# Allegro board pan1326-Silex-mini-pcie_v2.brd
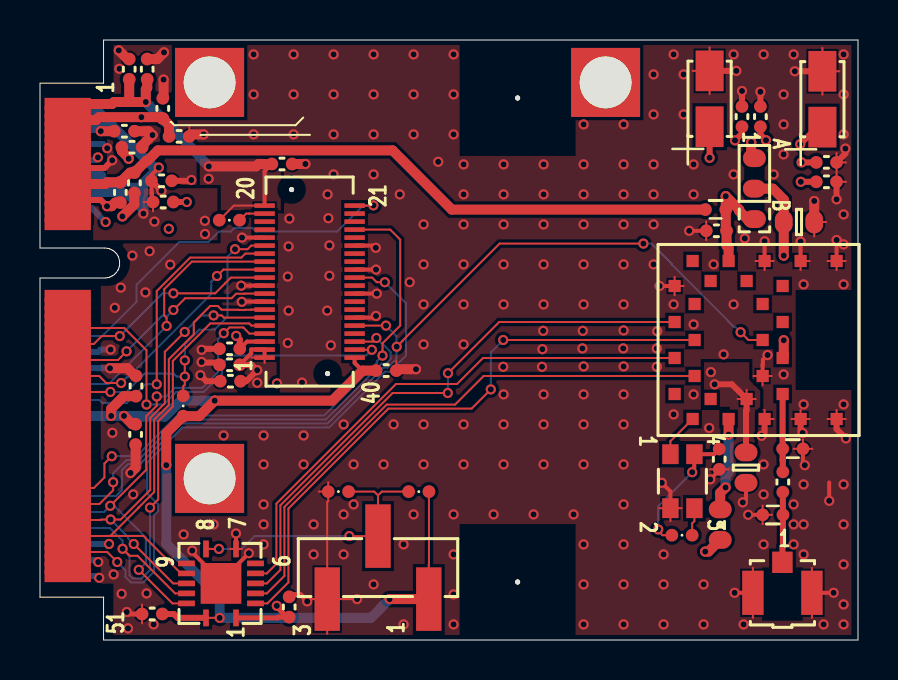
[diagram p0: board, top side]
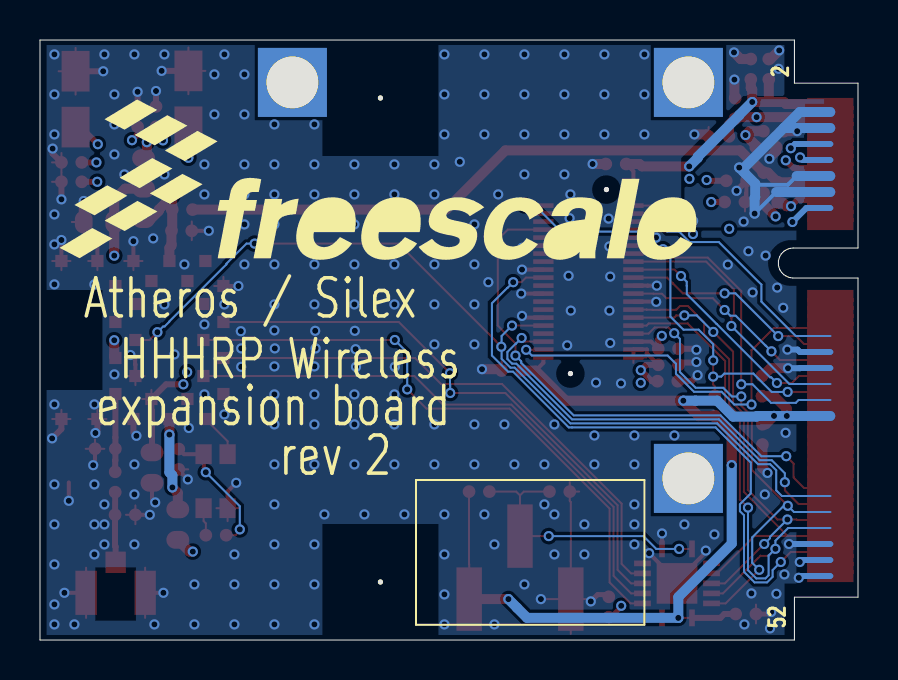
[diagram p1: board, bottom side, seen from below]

Outline 40.9 x 30 mm; copper layers: TOP, GND, PWR, BOTTOM. Coordinates in mm from the lower left corner of the outline.
Outline path: 0,27.84 0,19.6 3.24,19.6 3.4,19.58 3.48,19.56 3.64,19.48 3.7,19.44 3.84,19.3 3.92,19.16 3.98,18.96 3.98,18.74 3.96,18.66 3.92,18.54 3.9,18.5 3.82,18.38 3.7,18.26 3.6,18.2 3.48,18.14 3.4,18.12 3.26,18.1 0,18.1 0,2.14 3.18,2.14 3.18,0 40.9,0 40.9,30 3.18,30 3.18,27.84 0,27.84

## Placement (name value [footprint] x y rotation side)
C2  ASSEMBLE 0R  [CC0402_25]  37.14 7.9 270 top
C7  0.1uF  [CC0402_25]  5.61 1.3 180 top
C12  2.2UF  [CC0603_OV]  35.3 8.62 270 top
C15  1.0UF  [CC0402_25]  33.82 20.46 180 top
C16  2.2UF  [CC0603_OV]  37.95 20.9 0 top
C17  0.1uF  [CC0402_25]  12.46 1.65 90 top
C18  0.1uF  [CC0402_25]  33.96 9.04 270 top
C19  0.1uF  [CC0402_25]  9.48 13.76 180 top
C20  0.1uF  [CC0402_25]  9.48 14.56 180 top
C21  0.1uF  [CC0402_25]  9.52 12.94 180 top
C22  0.1uF  [CC0402_25]  17.31 13.47 0 top
C23  0.1uF  [CC0402_25]  12.1 23.8 0 top
C24  47uF  [CC3216]  39.12 27.04 90 top
C25  47uF  [CC3216]  33.48 27.06 90 top
C26  0.1uF  [CC0402_25]  35.1 26.17 90 top
C27  0.1uF  [CC0402_25]  39.32 23.88 0 top
C28  0.01UF  [CC0402_25]  36.02 26.17 90 top
C29  0.01UF  [CC0402_25]  39.32 22.91 0 top
C46  100PF  [CC0402_25]  4.22 25.44 0 top
C47  0.01UF  [CC0402_25]  4.6 24.64 0 top
C48  0.01UF  [CC0402_25]  6.08 22.96 0 top
C49  100PF  [CC0402_25]  6.16 21.9 0 top
C54  0.01UF  [CC0402_25]  4.02 22.38 270 top
C55  100PF  [CC0402_25]  4.72 22.86 270 top
C56  0.01UF  [CC0402_25]  6.96 25.18 0 top
C57  100PF  [CC0402_25]  6.14 26.58 90 top
C58  0.01UF  [CC0402_25]  4.46 28.54 90 top
C59  100PF  [CC0402_25]  5.36 28.54 90 top
C60  0.01UF  [CC0402_25]  4.78 10.28 270 top
C61  100PF  [CC0402_25]  4.8 12.7 90 top
J1  MINIPCI EDGE CONNECTOR  [CON2X26_MINI_PCIE_HALFSIZE]  13.38 15 270 top
J2  HDR 2X20  [HDR_2X20_0P4_SM]  13.48 17.92 90 top
J3  HDR 1X3  [HDR103_STAG_SM]  16.9 3.62 90 top
J4  U.FL  [CON_3_UFL_R_SMT]  37.12 2.36 0 top
L2  TBD  [IND_0402]  37.64 9.56 0 top
L3  TBD  [IND_0402]  36.64 6.26 180 top
L5  120 Ohm  [IND_0402]  33.78 21.52 0 top
NOREF  -  []  -0.02 17.56 0 top
NOREF#2  -  []  3.18 0 90 top
NOREF#3  -  []  65.58 169.66 90 top
NOREF#4  -  [unnamed#2]  8.48 27.88 0 top
NOREF#5  -  []  63.32 189.4 90 top
NOREF#6  -  [unnamed#2]  28.28 27.88 0 top
NOREF#7  -  []  3.18 30 0 top
NOREF#8  -  []  40.9 0 90 top
NOREF#9  -  []  -179.5 -280.6 0 top
NOREF#10  -  []  3.18 27.84 90 top
NOREF#11  -  []  0 19.6 90 top
NOREF#12  -  []  69.78 196.44 0 top
NOREF#13  -  [unnamed#2]  8.48 8.08 0 top
NOREF#14  -  []  399.68 196.44 0 top
NOREF#15  -  []  0 2.14 90 top
NOREF#16  -  []  63.4 174.28 90 top
NOREF#17  -  []  0 27.84 0 top
NOREF#18  -  []  39.92 19.5 180 bottom
R5  10.0K  [RC0402_25]  32.1 5.24 180 top
R6  10.0K  [RC0402_25]  18.94 7.42 180 top
R7  10.0K  [RC0402_25]  14.92 7.42 0 top
R8  22K  [RC0402_25]  7.16 11.7 90 top
R9  10.0K  [RC0402_25]  9.47 20.99 0 top
R13  0  [R603-X2]  35.72 23.33 270 top
R14  0  [RC0603_OV]  34.01 5.77 90 top
U1  PAN1326  [LGA24_0P9_9P2X9P7]  34.43 15 270 top
U4  TXB0104  [QFN14_RGY]  9.05 2.83 90 top
Y1  32.7680KHZ  [XTLOSC4_3P3X1P6_SM]  32.12 7.94 270 top

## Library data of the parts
C2 C7 C12 C15-C29 C46-C49 C54-C61 = CAP_NP
J1 = MINI_PCI_LATCH_52P
J2 = CONN_HDR_20X2
J3 = CONN_HDR_3X1
J4 = UFL
L2 L3 = BEAD
L5 = INDUCTOR_FERRITE
R5-R9 R14 = RES
R13 = RES_0603_X2: Tolerance: X; User Part Number: 470-80217
U1 = ENW898_24P
U4 = TXB0104
Y1 = OSC_4P

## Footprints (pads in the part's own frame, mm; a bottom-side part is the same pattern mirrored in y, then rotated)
CC0402_25
  round 0.635 smd: 1(-0.508,0) 2(0.508,0)
CC0603_OV
  oval 0.889x1.143 smd: 1(-0.762,0) 2(0.762,0)
CC3216
  rect 2.032x1.397 smd: 1(-1.397,0) 2(1.397,0)
CON2X26_MINI_PCIE_HALFSIZE
  round 0.254 hole 2.591 unplated: (-12.1,10.5) (12.1,10.5)
  rect 0.61x2.311 smd: 1(-11.8,-11.994) 2(-11.4,-11.994) 3(-11,-11.994) 4(-10.6,-11.994) 5(-10.2,-11.994) 6(-9.8,-11.994) 7(-9.4,-11.994) 8(-9,-11.994) 9(-8.6,-11.994) 10(-8.2,-11.994) 11(-7.8,-11.994) 12(-7.4,-11.994) 13(-7,-11.994) 14(-6.6,-11.994) 15(-6.2,-11.994) 16(-5.8,-11.994) 17(-2.2,-11.994) 18(-1.8,-11.994) 19(-1.4,-11.994) 20(-1,-11.994) 21(-0.6,-11.994) 22(-0.2,-11.994) 23(0.2,-11.994) 24(0.6,-11.994) 25(1,-11.994) 26(1.4,-11.994) 27(1.8,-11.994) 28(2.2,-11.994) 29(2.6,-11.994) 30(3,-11.994) 31(3.4,-11.994) 32(3.8,-11.994) 33(4.2,-11.994) 34(4.6,-11.994) 35(5,-11.994) 36(5.4,-11.994) 37(5.8,-11.994) 38(6.2,-11.994) 39(6.6,-11.994) 40(7,-11.994) 41(7.4,-11.994) 42(7.8,-11.994) 43(8.2,-11.994) 44(8.6,-11.994) 45(9,-11.994) 46(9.4,-11.994) 47(9.8,-11.994) 48(10.2,-11.994) 49(10.6,-11.994) 50(11,-11.994) 51(11.4,-11.994) 52(11.8,-11.994)
CON_3_UFL_R_SMT
  rect 1.016x1.067 smd: 1(0,1.524)
  rect 1.067x2.21 smd: 2(-1.476,0) 3(1.476,0)
HDR103_STAG_SM
  rect 3.175x1.27 smd: 1(-1.575,-2.54) 2(1.575,0) 3(-1.575,2.54)
HDR_2X20_0P4_SM
  round 0.254 hole 0.66 unplated: (-4.6,-0.9) (4.6,0.9)
  rect 0.229x1.016 smd: 1(-3.8,2.25) 2(-3.4,2.25) 3(-3,2.25) 4(-2.6,2.25) 5(-2.2,2.25) 6(-1.8,2.25) 7(-1.4,2.25) 8(-1,2.25) 9(-0.6,2.25) 10(-0.2,2.25) 11(0.2,2.25) 12(0.6,2.25) 13(1,2.25) 14(1.4,2.25) 15(1.8,2.25) 16(2.2,2.25) 17(2.6,2.25) 18(3,2.25) 19(3.4,2.25) 20(3.8,2.25) 21(3.8,-2.25) 22(3.4,-2.25) 23(3,-2.25) 24(2.6,-2.25) 25(2.2,-2.25) 26(1.8,-2.25) 27(1.4,-2.25) 28(1,-2.25) 29(0.6,-2.25) 30(0.2,-2.25) 31(-0.2,-2.25) 32(-0.6,-2.25) 33(-1,-2.25) 34(-1.4,-2.25) 35(-1.8,-2.25) 36(-2.2,-2.25) 37(-2.6,-2.25) 38(-3,-2.25) 39(-3.4,-2.25) 40(-3.8,-2.25)
IND_0402
  round 0.635 smd: 1(-0.508,0) 2(0.508,0)
LGA24_0P9_9P2X9P7
  rect 0.61x0.61 smd: 1(-2.7,-2.7) 2(-1.8,-1.7) 3(-0.9,-2.7) 4(0,-1.7) 5(0.9,-2.7) 6(1.8,-1.7) 7(2.7,-2.7) 8(3.95,-1.8) 9(2.95,-0.9) 10(3.95,0) 11(2.95,0.9) 12(3.95,1.8) 13(2.7,2.7) 14(1.8,1.7) 15(0.9,2.7) 16(0,1.7) 17(-0.9,2.7) 18(-1.8,1.7) 19(-2.7,2.7) 20(-3.95,1.8) 21(-2.95,0.9) 22(-3.95,0) 23(-2.95,-0.9) 24(-3.95,-1.8) A(-3.95,3.6) B(3.95,3.6) C(-3.95,5.4) D(3.95,5.4)
QFN14_RGY
  rect 0.838x0.279 smd: 1(-1.725,-0.75) 7(1.725,-0.75) 8(1.725,0.75) 14(-1.725,0.75)
  rect 0.279x0.838 smd: 2(-1,-1.725) 3(-0.5,-1.725) 4(0,-1.725) 5(0.5,-1.725) 6(1,-1.725) 9(1,1.725) 10(0.5,1.725) 11(0,1.725) 12(-0.5,1.725) 13(-1,1.725)
  rect 2.032x2.032 smd: 15(0,0)
R603-X2
  oval 0.889x1.143 smd: 1(-0.762,0) 2(0.762,0) 3(2.286,0)
RC0402_25
  round 0.635 smd: 1(-0.508,0) 2(0.508,0)
RC0603_OV
  oval 0.889x1.143 smd: 1(-0.762,0) 2(0.762,0)
unnamed#2
  rect 3.45x3.45 hole 2.591: (0,0)
XTLOSC4_3P3X1P6_SM
  rect 0.991x0.813 smd: 1(-1.35,-0.6) 2(1.35,-0.6) 3(1.35,0.6) 4(-1.35,0.6)

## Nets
GND: C7.2 C12.2 C15.2 C16.2 C17.2 C18.2 C19.2 C20.2 C21.2 C22.2 C23.2 C24.2 C25.2 C26.2 C27.2 C28.2 C29.2 C46.2 C47.2 C48.2 C49.2 C54.2 C55.2 C56.2 C57.2 C58.2 C59.2 C60.2 C61.2 J1.6(1.5V_1) J1.8(UIM_PWR) J1.9(GND1) J1.13(REFCLK+) J1.14(UIM_RESET) J1.24(+3.3VAUX) J1.26(GND9) J1.48(1.5V_3) J1.50(GND12) J1.52(3.3V_2) J2.8(B4) J2.10(B5) J2.16(B8) J2.26(B13) J2.29(A15) J2.32(B16) J2.35(A18) J3.3 J4.2(GND1) J4.3(GND2) L2.2 L3.2 R7.1 U1.1(GND1) U1.12(GND2) U1.14(GND3) U1.20(GND4#20) U1.A(GND4#A) U1.B(GND5) U1.C(GND6) U1.D(GND7) U4.7(GND) U4.15(EXP) Y1.2(GND)
BT_ACTIVE: J1.41(RESERVED5) J2.24(B12)
BT_CLK_REQ: J2.17(A9)
BT_CLKOUT: J2.22(B11)
BT_DISABLE: J2.23(A12)
BT_FREQUENCY: J2.37(A19)
BT_HOST_WAKE: J1.43(RESERVED6) J2.38(B19)
BT_PRIORITY: J2.25(A13)
BT_RESET_B: J1.42(LED_WWAN#) J2.36(B18) U1.16(S\H\U\T\D\)
BT_RF_3V3: C12.1 C20.1 C25.1 C26.1 C28.1 C56.1 C57.1 J1.3(RESERVED1) J2.3(A2) R13.1 U1.11(CL1.5_LDO_IN)
BT_UART_CTS: J1.45(RESERVED7) J2.6(B3) U4.11(B3)
BT_UART_CTS_1V8: U1.3(HCI_CTS) U4.4(A3)
BT_UART_RTS: J1.44(LED_WLAN#) J2.4(B2) U4.13(B1)
BT_UART_RTS_1V8: U1.4(HCI_RTS) U4.2(A1)
BT_UART_RX: J1.47(RESERVED8) J2.7(A4) U4.10(B4)
BT_UART_RX_1V8: U1.5(HCI_RX) U4.5(A4)
BT_UART_TX: J1.46(LED_WPAN#) J2.5(A3) U4.12(B2)
BT_UART_TX_1V8: U1.6(HCI_TX) U4.3(A2)
BT_VDDIO_1V8: C15.1 C17.1 C18.1 C24.1 C27.1 C29.1 L5.2 R5.2 R13.3 R14.1 U1.22(VDD_IO) U4.1(VCCA) Y1.4(VDD)
CLK32K: U1.8(SLOW_CLK_IN) Y1.1(CLKOUT)
DCDC_VDDIO_3V3: C7.1 C22.1 C23.1 C58.1 C59.1 C60.1 C61.1 J1.1(WAKE#) J1.32(SMB_DATA) J2.20(B10) J2.40(B20) J3.1 R6.1 R8.1 R9.1 U4.14(VCCB)
HMODE0: J2.19(A10) R9.2
WIFI_SDIO_CLK: J1.25(PERP0) J2.9(A5)
WIFI_SDIO_CMD: J1.29(GND5) J2.15(A8) R8.2
WIFI_SDIO_DAT0: J1.23(PERN0) J2.11(A6)
WIFI_SDIO_DAT1: J1.27(GND4) J2.12(B6)
WIFI_SDIO_DAT2: J1.28(1.5V_2) J2.13(A7)
WIFI_SDIO_DAT3: J1.30(SMB_CLK) J2.14(B7)
WL_RF_1V8: C54.1 C55.1 J1.11(REFCLK-) L5.1
WL_RF_3V3: C19.1 C21.1 C46.1 C47.1 C48.1 C49.1 J1.2(3.3V_1) J1.4(GND7) J1.10(UIM_DATA) J1.12(UIM_CLK) J2.1(A1) J2.2(B1)
WLAN_ACTIVE: J1.49(RESERVED9) J2.30(B15)
WLAN_RESET_B: J1.22(PERST#) J2.21(A11)
WLAN_WAKE: J1.21(GND3) J2.39(A20)
N16415: R5.1 Y1.3(CLKOE)
N18192: C2.2 J4.1(CTR) L3.1
N18200: C2.1 L2.1 U1.13(RF)
N28121: J3.2 R6.2 R7.2 U4.8(OE)
N39460: C16.1 R13.2 U1.15(MLDO_IN)
N39860: R14.2 U1.10(MLDO_OUT)

Pads without a net: J1 5 7 15 16 17 18 19 20 31 33 34 35 36 37 38 39 40 51; J2 18 27 28 31 33 34; U1 2 7 9 17 18 19 21 23 24; U4 6 9

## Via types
v1: diameter 0.508, hole 0.305, TOP to BOTTOM, 349 vias

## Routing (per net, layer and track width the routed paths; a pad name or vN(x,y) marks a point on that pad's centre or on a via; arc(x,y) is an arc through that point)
GND: length 120
  TOP w0.1: U1.1 31.73,18.16 ; U1.1 31.73,17.24 ; U1.1 32.19,17.7 ; 18.29,13.47 C22.2 17.82,13.94 ; R7.1 14.41,7.89 ; R7.1 13.94,7.42 ; R7.1 14.41,6.95 14.36,6.9 J3.3 ; 13.57,2.05 J3.3 ; J3.3 14.36,0.31 ; J3.3 v1(15.86,2.05) ; 37.68,9.56 L2.2 ; L2.2 38.62,9.56 ; L2.2 38.15,10.03 ; C25.2 33.48,29.62 ; C25.2 33.48,27.29 ; C25.2 32.63,28.46 ; 39.31,20.9 C16.2 38.71,20.18 ; U1.14 36.59,13.2 ; U1.14 36.13,12.74 ; U1.14 35.67,13.2 ; 10.09,4.55 U4.7 9.51,4.55 ; C24.2 39.12,29.6 ; C24.2 39.12,27.27 ; C24.2 39.97,28.44 ; 39.37,18.95 U1.C ; U1.C 39.83,18.49 ; U1.C 40.29,18.95 ; U1.B 38.03,11.51 ; U1.B 38.49,11.05 ; U1.B 37.57,11.05 ; 38.49,18.95 U1.A 38.03,18.49 ; 7.47,25.65 C56.2 7.94,25.18 ; 38.6,3.62 J4.3 38.6,1.1 ; L3.2 36.13,6.73 ; L3.2 36.6,6.26 ; L3.2 36.13,5.79 ; 40.3,22.91 C29.2 39.83,23.38 ; 33.31,19.99 C15.2 33.31,20.93 ; 35.64,3.62 J4.2 35.64,1.1 ; C27.2 40.3,23.88 ; C27.2 39.83,24.35 ; C27.2 39.83,23.41 ; 5.1,1.77 C7.2 5.1,0.83 ; 31.52,5.94 Y1.2 ; Y1.2 30.96,6.59 ; Y1.2 32.08,6.59 ; 33.49,8.53 C18.2 34.43,8.53 ; U1.D 40.29,11.05 ; U1.D 39.37,11.05 ; U1.D 39.83,11.51 ; 36.23,18.49 U1.20 ; U1.20 35.77,18.95 ; U1.20 36.69,18.95 ; 36.69,11.05 U1.12 36.23,11.51
  TOP w0.2: v1(36.38,14.25) 36.14,14.01 36.14,13.82 36.13,13.76 36.13,13.75 U1.14 ; C18.2 33.96,8.48 v1(33.51,8.03) ; v1(10.09,16.91) 10.1,16.92 J2.8 ; J4.2 v1(34.73,2.36) ; 9.05,2.95 7.61,4.39 v1(7.61,4.47) ; 9.05,2.95 v1(10.44,4.34) ; 9.05,2.95 U4.15 9.05,2.67 ; v1(10.06,17.72) 10.51,17.72 10.52,17.72 J2.10 ; U1.C v1(39.83,20) ; v1(9.8,5.33) U4.7 ; v1(16.8,16.2) 16.72,16.12 J2.35 ; L2.2 38.15,8.83 v1(38.24,8.74) ; 39.46,7.88 v1(39.46,6.96) ; J2.32 v1(16.84,17.32) ; U1.A v1(38.03,19.92) ; U1.1 v1(30.98,17.7) ; J2.29 v1(16.8,18.52) ; C12.2 35.3,7.04 v1(35.14,6.88) ; L3.2 v1(35.41,6.26) ; U1.20 v1(36.23,19.94) ; C15.2 v1(32.46,20.46) ; J2.26 16.68,19.72 v1(16.79,19.61) ; v1(31.09,7.86) 31.52,7.43 Y1.2 ; J2.16 v1(10.1,20.12) ; J4.3 v1(39.68,2.36) ; 36.23,10.36 v1(36.08,10.21)
  TOP w0.25: v1(4.34,1.4) 4.44,1.3 C7.2 ; v1(13.36,1.93) 13.02,2.27 12.57,2.27 C17.2
  TOP w0.3: U1.12 36.23,10.36 ; U1.B 38.03,10.45 v1(38.13,10.35) ; C48.2 7.53,22.96 v1(7.57,23) ; v1(8.02,13.24) 8.32,12.94 C21.2 ; J1.9 3.23,23.6 v1(3.61,23.99) ; C49.2 v1(7.34,21.9) ; C19.2 8.86,13.87 8.11,13.87 v1(8.08,13.9) ; C29.2 v1(39.83,22.03) ; C25.2 v1(34.82,28.46) ; v1(40.27,24.57) 40.27,24.32 C27.2 ; J1.13 3.04,22 v1(3.35,21.69) ; 36.18,10.28 36.11,10.21 v1(36.08,10.21) ; U1.D 39.83,10.55 v1(40.3,10.08) ; C24.2 v1(37.74,28.44) ; C26.2 v1(35.1,27.45) ; v1(8.08,14.51) 8.13,14.56 C20.2 ; C28.2 v1(36.02,27.41)
  TOP w0.5: C47.2 5.11,24.73 v1(5.62,25.25) 5.43,25.44 C46.2 ; v1(3.5,13.59) 4.37,13.59 4.75,13.21 C61.2 ; C60.2 4.78,8.61 v1(4.53,8.35) ; C54.2 3.76,21.87 3.58,21.69 v1(3.35,21.69) ; v1(6.18,28.02) 6.18,27.13 C57.2 ; C16.2 v1(38.71,21.95) ; C56.2 7.57,25.28 v1(8.18,25.28) ; C22.2 17.89,13.54 v1(18.8,13.54) ; C23.2 v1(13.27,23.8) ; C59.2 5.87,29.05 v1(6.2,29.38) ; v1(3.94,29.48) 4.37,29.05 C58.2 ; C55.2 4.72,21.78 v1(4.12,21.18)
  BOTTOM w0.3: J1.14 2.58,21.6 v1(3.28,20.9) ; J1.52 2.87,3.2 v1(2.96,3.11) ; v1(3.53,14.52) 3.03,14.52 2.91,14.4 J1.24 ; J1.48 2.94,4.8 v1(3.45,4.8) ; v1(3.5,13.59) 2.9,13.59 2.89,13.6 J1.26 ; J1.6 3.15,24.8 v1(3.36,24.59) ; J1.50 2.81,4 v1(2.91,3.9) ; v1(2.9,24.13) 2.77,24 J1.8
  vias: v1(3.62,10.36) v1(3.68,3.28) v1(3.74,16.61) v1(3.97,28.56) v1(4.04,17.62) v1(4.08,2.31) v1(4.4,0.58) v1(4.62,19.22) v1(4.66,7.28) v1(5.27,17.38) v1(5.33,2.33) v1(5.48,19.44) v1(5.68,0.78) v1(6.51,18.77) v1(7.18,5.28) v1(8.68,5.78) v1(9.18,10.23) v1(10.68,29.28) v1(10.68,27.28) v1(10.68,25.28) v1(11.18,10.23) v1(11.18,8.78) v1(11.18,6.78) v1(11.18,5.78) v1(11.18,4.78) v1(11.85,12.83) v1(12.39,18.17) v1(12.39,14.85) v1(12.47,21.07) v1(12.43,19.68) v1(12.43,16.47) v1(12.68,29.28) v1(12.68,27.28) v1(12.68,25.28) v1(13.1,12.87) v1(13.18,10.23) v1(13.18,8.78) v1(13.68,5.78) v1(13.68,4.28) v1(14.38,22.28) v1(14.42,21.09) v1(14.36,16.47) v1(14.47,19.73) v1(14.47,18.21) v1(14.54,14.73) v1(14.68,29.28) v1(14.68,27.28) v1(14.68,25.28) v1(14.68,23.28) v1(15.18,10.78) v1(15.18,6.28) v1(15.18,4.28) v1(15.68,8.78) v1(15.68,6.78) v1(16.68,29.28) v1(16.68,27.28) v1(16.68,25.28) v1(16.68,23.28) v1(16.68,2.78) v1(17.18,8.78) v1(17.68,10.78) v1(17.99,22.28) v1(18.18,4.78) v1(18.18,0.78) v1(18.48,17.89) v1(18.68,29.28) v1(18.68,27.28) v1(18.68,25.28) v1(18.68,6.28) v1(19.18,20.78) v1(19.18,18.78) v1(19.18,16.78) v1(19.18,14.78) v1(19.18,10.78) v1(19.18,8.78) v1(19.91,23.91) v1(20.68,29.28) v1(20.68,27.28) v1(20.68,25.28) v1(20.68,6.28) v1(20.68,4.28) v1(20.68,2.28) v1(20.68,0.78) v1(21.18,23.78) v1(21.18,22.28) v1(21.18,20.78) v1(21.18,18.78) v1(21.18,16.78) v1(21.18,14.78) v1(21.18,10.78) v1(21.18,8.78) v1(22.68,6.28) v1(23.18,23.78) v1(23.18,22.28) v1(23.18,20.78) v1(23.18,18.78) v1(23.18,16.78) v1(23.16,13.66) v1(23.18,12.28) v1(23.18,10.78) v1(23.18,8.78) v1(24.68,6.28) v1(25.12,14.54) v1(25.1,13.66) v1(25.18,23.78) v1(25.18,22.28) v1(25.18,20.78) v1(25.18,18.78) v1(25.18,16.78) v1(25.16,15.46) v1(25.18,12.28) v1(25.18,10.78) v1(25.18,8.78) v1(26.68,6.28) v1(27.12,14.58) v1(27.18,25.78) v1(27.18,23.78) v1(27.18,22.28) v1(27.18,20.78) v1(27.18,18.78) v1(27.18,16.78) v1(27.14,15.46) v1(27.18,13.68) v1(27.18,12.28) v1(27.18,10.78) v1(27.18,8.78) v1(27.18,4.78) v1(27.18,2.78) v1(27.18,0.78) v1(29.18,25.78) v1(29.18,23.78) v1(29.18,22.28) v1(29.18,20.78) v1(29.18,18.78) v1(29.18,16.78) v1(29.18,15.48) v1(29.16,14.58) v1(29.18,13.68) v1(29.18,12.28) v1(29.18,10.78) v1(29.18,8.78) v1(29.18,6.78) v1(29.18,4.78) v1(29.18,2.78) v1(29.18,0.78) v1(30.68,28.28) v1(30.68,26.28) v1(30.68,23.78) v1(30.68,22.28) v1(30.68,20.78) v1(30.68,18.78) v1(30.86,15.44) v1(30.84,14.58) v1(30.84,13.66) v1(31.18,4.28) v1(31.18,2.78) v1(31.18,0.78) v1(31.68,29.28) v1(31.68,16.78) v1(31.68,11.28) v1(32.18,28.28) v1(32.18,26.28) v1(32.68,23.78) v1(32.68,22.28) v1(32.68,15.78) v1(32.68,12.28) v1(33.18,2.78) v1(33.18,0.78) v1(33.46,10.6) v1(33.68,18.78) v1(34.18,14.28) v1(34.68,29.28) v1(34.68,23.28) v1(34.68,16.78) v1(35.18,0.78) v1(35.24,20.08) v1(36.18,29.28) v1(36.18,8.78) v1(36.18,7.28) v1(36.18,4.78) v1(36.68,23.28) v1(37.18,27.28) v1(37.18,25.78) v1(37.18,24.28) v1(37.18,13.28) v1(37.68,29.28) v1(37.68,6.78) v1(37.68,5.78) v1(37.68,4.78) v1(38.18,17.78) v1(38.18,11.78) v1(38.18,7.78) v1(38.18,5.78) v1(38.18,4.28) v1(39.18,0.78) v1(40.18,29.28) v1(40.18,27.28) v1(40.18,25.28) v1(40.18,21.28) v1(40.18,19.78) v1(40.18,17.78) v1(40.18,11.78) v1(40.18,7.78) v1(40.18,5.78) v1(40.18,3.78) v1(40.18,1.78) v1(40.18,0.78)
BT_ACTIVE: length 27.6
  TOP w0.1: v1(3.59,9.19) 3.22,8.82 3.22,8.13 2.69,7.6 J1.41 ; v1(17.13,14.22) 17.13,14.84 18.01,15.72 18.01,20.02 17.51,20.52 J2.24
  BOTTOM w0.1: v1(17.13,14.22) 16.84,13.93 16.84,13.86 14.21,11.23 6.87,11.23 4.83,9.19 v1(3.59,9.19)
BT_HOST_WAKE: length 22.2
  TOP w0.1: J1.43 2.97,6.8 3.66,7.49 v1(3.66,7.89) ; v1(16.82,15.1) 16.64,14.92 J2.38
  BOTTOM w0.1: v1(16.82,15.1) 17.11,14.81 17.12,14.81 17.53,14.4 17.53,14.05 17.29,13.82 17.08,13.82 14.3,11.03 6.95,11.03 4.91,8.99 4.31,8.99 3.66,8.34 v1(3.66,7.89)
BT_RESET_B: length 45.8
  TOP w0.1: v1(35.03,15.39) 35.42,15 U1.16 ; v1(30.17,19.82) 22.98,19.82 18.12,14.96 18.12,14.95 v1(17.84,14.66) ; v1(17.3,15.72) J2.36
  BOTTOM w0.1: v1(17.3,15.72) 17.82,15.2 17.82,14.66 ; v1(17.84,14.66) 17.83,14.66 17.82,14.66 ; 17.82,14.66 17.82,14.06 17.38,13.62 17.17,13.62 14.38,10.83 7.04,10.83 5,8.79 4.39,8.79 4.09,8.49 4.09,7.48 3.81,7.2 J1.42 ; v1(35.03,15.39) 34.74,15.68 34.67,15.68 34.44,15.91 34.44,15.92 31.58,18.78 31.58,18.82 30.57,19.82 v1(30.17,19.82)
BT_RF_3V3: length 18
  TOP w0.1: 34.87,12.05 U1.11 ; U1.11 35.33,12.51 ; U1.11 35.79,12.05
  TOP w0.2: J2.3 10.35,14.92 C20.1
  TOP w0.3: C20.1 9.99,15.03 v1(9.81,15.21) ; C25.1 v1(33.48,24.11) ; C28.1 36.02,25.27 v1(36.3,24.99) ; C26.1 35.1,25.33 v1(34.75,24.98) ; v1(33.73,12.78) 34.6,12.78 U1.11 35.33,11.5 35.3,11.47 C12.1
  TOP w0.5: C56.1 6.45,25.76 C57.1 6.07,26.14 v1(5.07,26.14) 2.95,26.14 2.81,26 J1.3 ; v1(35.56,24.89) 35.56,24.25 R13.1
  vias: v1(6.44,20.56) v1(33.54,13.39)
BT_UART_CTS: length 22.9
  TOP w0.1: J1.45 3.04,6 3.07,6.02 v1(3.53,6.02) 4.03,6.02 5.51,7.5 5.51,11.1 6.24,11.84 6.24,14.41 v1(7.24,15.4) ; J2.6 9.19,16.12 9.08,16.23 v1(8.68,16.23) ; v1(4.69,4.8) 6.66,2.83 U4.11
  BOTTOM w0.1: v1(3.53,6.02) 4.4,5.15 4.4,5.09 v1(4.69,4.8) ; v1(7.24,15.4) 8.06,16.23 v1(8.68,16.23)
BT_UART_CTS_1V8: length 28.8
  TOP w0.1: U1.3 22.96,15.9 v1(20.4,13.34) ; U4.4 11.34,2.83 12.02,3.51 12.02,6.74 17.63,12.35 v1(20.39,12.35)
  BOTTOM w0.1: v1(20.39,12.35) 20.39,12.75 20.4,12.76 v1(20.4,13.34)
BT_UART_RTS: length 23.9
  TOP w0.1: J2.4 10.47,15.32 10.16,15.63 9.47,15.63 v1(9.19,15.34) ; v1(3.51,6.71) 5.31,8.51 5.31,11.19 5.84,11.71 v1(5.84,12.18) ; v1(4.94,3.51) 6.62,1.83 U4.13
  BOTTOM w0.1: 3.46,6.66 v1(3.51,6.71) ; 3.46,6.66 3.76,6.66 5.29,5.13 5.29,3.86 v1(4.94,3.51) ; 3.46,6.66 3.2,6.4 J1.44 ; v1(5.84,12.18) 6.3,12.18 6.74,12.61 8.12,12.61 8.9,13.4 8.9,15.05 v1(9.19,15.34)
BT_UART_RTS_1V8: length 30.7
  TOP w0.1: U4.2 11.37,1.83 12.42,2.88 12.42,6.57 17.42,11.57 21.58,11.57 v1(22.54,12.53) ; U1.4 v1(23.16,15)
  BOTTOM w0.1: v1(22.54,12.53) 22.54,14.38 v1(23.16,15)
BT_UART_RX: length 23.1
  TOP w0.1: U4.10 7.05,3.33 5.17,5.2 3.52,5.2 ; 3.52,5.2 3.28,5.2 3.28,5.2 J1.47 ; 3.52,5.2 4.93,6.61 4.93,6.62 5.71,7.4 5.71,11.02 6.44,11.75 6.44,14.04 7.69,15.29 7.69,15.88 8.51,16.7 8.89,16.7 9.08,16.51 9.91,16.51 9.92,16.5 10.26,16.5 10.27,16.51 10.56,16.51 10.57,16.52 J2.7
BT_UART_RX_1V8: length 27.2
  TOP w0.1: U1.5 22.15,14.1 20.85,12.8 17.8,12.8 11.82,6.82 11.82,3.81 11.34,3.33 U4.5
BT_UART_TX: length 26.6
  TOP w0.1: v1(4.13,4.56) 4.41,4.27 4.42,4.27 4.48,4.21 4.88,4.21 6.76,2.33 U4.12 ; J2.5 10.57,15.72 10.47,15.83 8.51,15.83 6.64,13.95 6.64,11.67 5.91,10.94 5.91,7.03 v1(5.5,6.62)
  BOTTOM w0.1: v1(5.5,6.62) 5.5,3.49 5.09,3.08 4.63,3.08 4.47,3.24 4.47,4.22 4.13,4.56 v1(4.13,4.56) 4.13,4.96 3.49,5.6 J1.46
BT_UART_TX_1V8: length 28.5
  TOP w0.1: U4.3 11.34,2.33 12.22,3.21 12.22,6.65 17.34,11.77 20.75,11.77 22.18,13.2 U1.6
BT_VDDIO_1V8: length 19.4
  TOP w0.1: v1(30.91,5.53) 30.91,5.45 31.12,5.24 R5.2
  TOP w0.2: v1(32.61,8.39) 32.61,8.52 32.71,8.62 32.71,9.28 Y1.4 33.7,9.29 33.96,9.55 C18.1
  TOP w0.25: U4.1 11.88,1.11 11.92,1.14 12.35,1.14 ; 12.35,1.14 C17.1 ; 12.35,1.14 11.85,1.64 11.85,1.7 v1(11.84,1.71)
  TOP w0.3: C29.1 v1(38.04,22.91) ; v1(38.01,24.79) 38.86,25.64 C24.1 ; C27.1 v1(38.08,23.88)
  TOP w0.5: v1(33.26,4.42) 33.42,4.42 R14.1 ; U1.22 34.43,19.6 34.33,19.71 34.33,19.79 C15.1 34.29,20.5 L5.2 v1(34.29,22.19) 34.96,21.52 34.96,21.45 35.37,21.04 R13.3
  BOTTOM w0.1: v1(30.91,5.53) 30.91,6.69 v1(32.61,8.39)
CLK32K: length 2.2
  TOP w0.1: U1.8 31.52,9.94 Y1.1
DCDC_VDDIO_3V3: length 83.8
  TOP w0.1: R6.1 19.45,3.79 19.44,3.78 J3.1 ; U4.14 v1(8.98,1.11) ; J2.20 9.69,21.72 R9.1
  TOP w0.2: J2.20 11.23,23.44 C23.1 ; 16.12,13.47 15.73,13.86 J2.40
  TOP w0.3: U4.14 6.88,1.11 6.69,1.3 C7.1
  TOP w0.5: v1(3.56,11.2) 3.56,11.56 4.19,12.19 C61.1 ; C60.1 4.61,10.79 4.2,11.2 v1(4.2,11.2) ; C22.1 16.12,13.47 14.62,11.97 v1(8.73,11.97) 7.96,11.19 R8.1 6.31,10.35 v1(6.31,8.74) ; 4.42,26.9 3.7,26.9 3.6,26.8 J1.1 ; 4.42,26.9 4.46,26.94 C58.1 ; 4.42,26.9 v1(5.29,26.9) 5.29,27.53 5.36,27.6 5.36,27.61 C59.1 ; C23.1 10.92,23.8 10.8,23.68 v1(8.44,23.68) ; J3.1 v1(17.48,2.05)
  PWR w0.5: v1(8.44,23.68) 8.44,22.03 7.64,21.23 7.64,17.06 8.02,16.68 8.02,15.51 8.73,14.8 v1(8.73,11.97)
  BOTTOM w0.5: v1(3.56,11.2) 3.5,11.2 3.5,11.2 ; v1(17.48,2.05) 17.05,1.62 17.05,1.61 16.55,1.11 v1(8.98,1.11) 8.98,2.15 6.31,4.82 v1(6.31,8.74) ; 3.5,11.2 4.2,11.2 ; 3.5,11.2 J1.32 ; 4.2,11.2 5.04,11.2 5.07,11.17 6.25,11.17 7.04,11.97 8.13,11.97 8.13,11.97 v1(8.73,11.97) ; 4.2,11.2 v1(4.2,11.2) ; v1(8.44,23.68) 8.01,24.11 8.01,24.16 5.94,26.23 5.94,26.24 v1(5.29,26.9)
  vias: v1(8.43,23.06)
HMODE0: length 1.4
  TOP w0.1: R9.2 10.31,21.32 10.46,21.32 10.47,21.32 J2.19
WIFI_SDIO_CLK: length 11.2
  TOP w0.1: v1(6.67,16.5) 7.26,17.09 9.58,17.09 9.8,17.31 10.23,17.31 10.24,17.32 J2.9 ; J1.25 3.9,14 4.04,14.14 4.04,14.15 v1(4.33,14.43)
  BOTTOM w0.1: v1(4.33,14.43) 4.61,14.72 4.62,14.72 6.11,16.21 6.38,16.21 v1(6.67,16.5)
WIFI_SDIO_CMD: length 16.7
  TOP w0.1: v1(9.75,19.54) 10.38,19.54 10.56,19.72 J2.15 ; v1(3.52,12.4) 3.06,12.4 3.06,12.4 J1.29 ; R8.2 7.16,12.69 7.24,12.77 v1(7.24,13.17) v1(7.24,13.98)
  BOTTOM w0.1: v1(7.24,13.17) 6.84,13.17 6.69,13.32 5.23,13.32 4.31,12.4 v1(3.52,12.4) ; v1(9.75,19.54) 9.38,19.17 9.38,16.17 8.73,15.52 7.97,15.52 7.24,14.79 v1(7.24,13.98)
WIFI_SDIO_DAT0: length 11.2
  TOP w0.1: J1.23 2.69,14.8 3.09,15.2 v1(3.99,15.2) ; v1(6.67,17.33) 8.76,17.33 9.25,17.82 9.25,17.83 9.54,18.12 J2.11
  BOTTOM w0.1: v1(6.67,17.33) 6.13,17.33 v1(3.99,15.2)
WIFI_SDIO_DAT1: length 12.7
  TOP w0.1: v1(8.85,18.2) 9.17,18.52 J2.12 ; v1(4.05,12.85) 3.31,12.85 2.96,13.2 J1.27
  BOTTOM w0.1: v1(4.05,12.85) 4.34,13.14 4.4,13.14 7.07,15.81 7.07,15.81 8.56,17.29 8.56,17.7 8.56,17.71 8.56,17.91 v1(8.85,18.2)
WIFI_SDIO_DAT2: length 13.6
  TOP w0.1: J2.13 7.59,18.92 6.21,17.54 6.21,16.22 6.33,16.1 v1(6.33,15.7)
  BOTTOM w0.1: J1.28 3.43,12.8 v1(6.33,15.7)
WIFI_SDIO_DAT3: length 15.7
  TOP w0.1: v1(5.84,12.79) 5.84,17.45 7.51,19.12 10.07,19.12 10.27,19.32 J2.14
  BOTTOM w0.1: J1.30 2.97,12 3.11,11.86 4.34,11.86 5.27,12.79 v1(5.84,12.79)
WL_RF_1V8: length 33.8
  TOP w0.5: J1.11 3.26,22.8 3.35,22.89 C54.1 4.5,23.37 C55.1 5.32,23.97 5.38,23.97 5.89,24.48 17.63,24.48 20.59,21.52 L5.1
WL_RF_3V3: length 39.1
  TOP w0.1: 5.18,21.9 C49.1 ; C49.1 5.65,21.43 ; C49.1 5.65,22.37 ; 10.57,14.12 J2.1 11.23,13.85
  TOP w0.2: 5.58,21.96 5.58,23.26 v1(5.94,23.62) ; C19.1 10.56,14.33 10.56,14.53 11.22,14.53 J2.2 J2.1
  TOP w0.3: C21.1 10.31,12.94 v1(10.86,13.49) 10.59,13.76 9.99,13.76 C19.1 ; C48.1 5.57,22.96 v1(6.07,22.46)
  TOP w0.5: C46.1 v1(3.04,25.44) ; C47.1 4.09,24.45 4.43,24.11 v1(4.43,24.06)
  PWR w0.5: v1(10.86,12.86) v1(10.86,13.49) 10.86,15.04 8.24,17.66 8.24,20.35 8.24,20.36 v1(8.24,20.96)
  BOTTOM w0.2: 3.07,23.2 3.51,22.76 5.05,22.76 5.58,23.3 5.62,23.3 ; 4.09,22.4 v1(5.17,21.32)
  BOTTOM w0.5: J1.4 3.71,25.6 ; 3.71,25.6 2.91,26.4 J1.2 ; 3.71,25.6 5.69,23.62 v1(5.94,23.62) 5.14,22.82 5.14,22.14 5.17,22.11 v1(5.17,21.32) ; 3.07,23.2 J1.10 ; J1.12 4.09,22.4
  vias: v1(5.72,20.92) v1(8.25,20.3)
WLAN_ACTIVE: length 32
  TOP w0.1: J2.30 16.61,18.12 16.84,17.89 v1(17.24,17.89) ; v1(3.86,3.9) 3.36,4.4 J1.49
  BOTTOM w0.1: v1(17.24,17.89) 17.53,17.6 17.54,17.6 18.3,16.84 18.3,14.22 17.5,13.42 17.25,13.42 14.46,10.63 14.3,10.63 7.12,10.63 5.36,8.87 5.36,7.33 5.9,6.79 5.9,6.44 5.7,6.24 5.7,3.41 5.17,2.88 4.55,2.88 4.27,3.16 4.27,3.49 v1(3.86,3.9)
WLAN_RESET_B: length 19.6
  TOP w0.1: v1(16.67,21.73) 16.66,21.72 J2.21
  BOTTOM w0.1: v1(16.67,21.73) 16.16,21.73 14.85,20.42 10.8,20.42 10.62,20.6 9.72,20.6 9.54,20.42 8.94,20.42 8.42,19.9 6.96,19.9 4.83,17.77 4.83,16.92 3.11,15.2 J1.22
WLAN_WAKE: length 20.7
  TOP w0.1: v1(16.59,14.51) 15.74,14.51 J2.39 ; v1(5.33,11.77) 5.33,14.48 4.21,15.6 J1.21
  BOTTOM w0.1: v1(5.33,11.77) 6.18,11.77 6.82,12.41 8.2,12.41 9.1,13.31 9.1,13.81 9.52,14.22 16.31,14.22 v1(16.59,14.51)
N16415: length 1.4
  TOP w0.1: Y1.3 32.72,5.94 32.61,5.83 R5.1
N18192: length 3.5
  TOP w0.3: C2.2 L3.1 37.15,4.7 37.12,4.67 J4.1
N18200: length 3.9
  TOP w0.3: C2.1 37.14,8.98 37.13,8.98 L2.1 37.13,10.13 37.13,10.13 U1.13
N28121: length 14.1
  TOP w0.1: 16.9,7.23 17.09,7.42 R6.2 ; 16.9,7.23 J3.2 v1(15.46,5.19) ; 16.9,7.23 16.71,7.42 R7.2 ; U4.8 v1(8.95,4.55)
  BOTTOM w0.1: v1(8.95,4.55) 10.09,4.55 10.73,5.19 v1(15.46,5.19)
N39460: length 9.6
  TOP w0.5: v1(37.19,14.99) 37.19,14.16 U1.15 ; R13.2 36.64,22.57 37.19,22.02 C16.1 v1(37.19,19.22)
  PWR w0.5: v1(37.19,19.22) v1(37.19,14.99)
N39860: length 4.7
  TOP w0.5: R14.2 34.01,7.36 v1(34.28,7.63) ; v1(34.43,10.27) U1.10
  BOTTOM w0.5: v1(34.28,7.63) 34.28,8.23 34.43,8.38 v1(34.43,10.27)

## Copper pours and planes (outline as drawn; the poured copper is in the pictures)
GND on TOP: 3.67,0.25 3.67,2.82 3.04,2.82 3.04,17.71 3.4,17.71 4.46,18.58 3.93,19.84 8.86,19.84 9,19.98 9,21.45 12.13,21.45 12.13,24.19 7.86,24.19 7.86,22.7 3.35,22.7 3.35,27.28 3.68,27.28 3.68,29.75 40.57,29.75 40.57,0.25 ; 3 cut-outs
GND on BOTTOM: 3.67,0.25 3.67,2.82 3.08,2.82 3.08,17.71 3.4,17.71 4.5,18.83 3.45,19.99 3.08,19.99 3.08,20.5 8.52,20.5 8.7,20.68 8.7,24.1 5.68,27.12 3.84,27.12 3.68,27.28 3.68,29.75 40.57,29.75 40.57,0.25 ; 5 cut-outs
GND on GND: 3.67,0.25 3.67,2.82 0.68,2.82 0.66,17.71 3.4,17.71 4.5,18.83 3.45,19.99 0.68,19.99 0.68,27.28 3.68,27.28 3.68,29.75 40.57,29.75 40.57,0.25
BT_RF_3V3 on TOP: 33.2,13.89 33.2,11.66 34.49,11.66 34.49,8.85 35.74,8.85 35.74,11.4 36.01,11.67 36.01,12.46 35.46,13.01 35.46,13.89
BT_RF_3V3 on PWR: 3.29,17.71 4.54,18.84 3.31,19.99 3.31,27.28 3.68,27.28 3.68,29.75 37.45,29.75 37.45,23.45 31.72,23.45 31.63,23.54 31.63,15.77 34.14,13.26 34.14,12.48 17.39,12.48 10.29,5.38 10.29,0.25 3.67,0.25 3.67,2.82 3.29,2.82
BT_VDDIO_1V8 on PWR: 31.76,23.35 31.76,15.81 34.23,13.34 34.23,12.39 17.67,12.39 10.55,5.27 10.55,0.25 40.61,0.25 40.61,29.75 37.54,29.75 37.54,23.35
DCDC_VDDIO_3V3 on TOP: 7.99,24.13 7.99,22.75 9.04,22.75 9.04,21.49 12.04,21.49 12.04,24.13
WL_RF_3V3 on TOP: 10.02,14.65 10.02,12.59 11.83,12.59 11.83,14.65
WL_RF_3V3 on TOP: 2.66,22.59 2.66,19.99 8.87,19.99 8.87,22.59
WL_RF_3V3 on BOTTOM: 1.69,27.04 1.69,20.63 8.68,20.63 8.68,24.03 5.67,27.04

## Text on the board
Ref Des/Silkscreen Bottom: rev 2 | HHHRP Wireless | expansion board | Atheros / Silex
DISPLAY_TOP: FIGURE | SIZE | 0.3048 | 2.5908 | 0.6604 | DRILL CHART: TOP to BOTTOM | ALL UNITS ARE IN MILLIMETERS | TOLERANCE | +0.0762/-0.0762 | +0.0508/-0.0508 | +0.1016/-0.0 | +0.1016/-0.1016 | PLATED | NON-PLATED | QTY | 349 | 3 | 2
